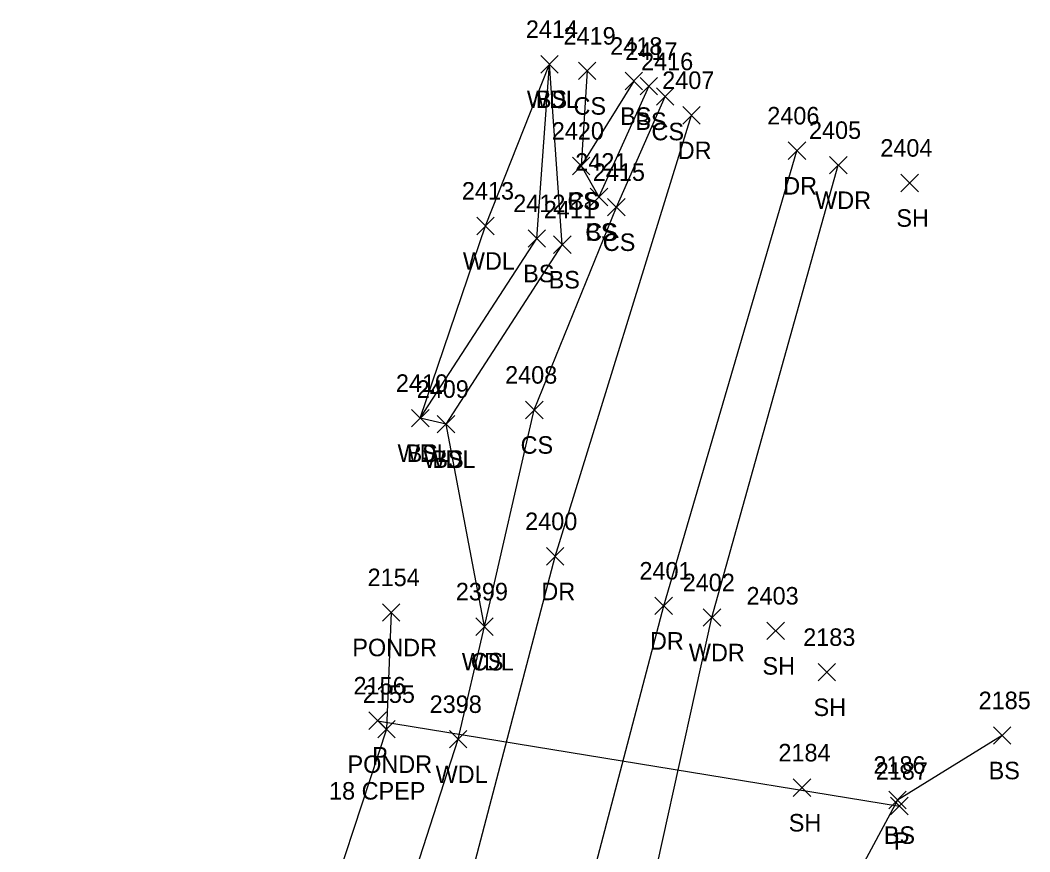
# Model space of a CAD drawing. Extents: x 1761340 to 1763889, y 696770 to 706023.
# Drawn here: x 1761653.6 to 1761768.9, y 701049.7 to 701144.6 of the extents above; entities that cross this region are included whole.
import ezdxf

# ---------------------------------------------------------------- set-up
doc = ezdxf.new("R2010")
doc.units = 0
for name, color, linetype in [('D_A', 7, 'Continuous'), ('D_C', 7, 'Continuous'), ('D_I', 7, 'Continuous'), ('D_TIC', 7, 'Continuous'), ('DCP', 7, 'Continuous'), ('L_A', 7, 'Continuous'), ('L_I', 7, 'Continuous'), ('L_TIC', 7, 'Continuous'), ('LAWA', 7, 'Continuous'), ('LAWE', 7, 'Continuous'), ('LELB', 7, 'Continuous'), ('R_A', 7, 'Continuous'), ('R_I', 7, 'Continuous'), ('R_TIC', 7, 'Continuous'), ('RDP', 7, 'Continuous')]:
    doc.layers.add(name, color=color, linetype=linetype)

msp = doc.modelspace()

# ---------------------------------------------------------------- linework, layer by layer
at = {"layer": 'D_TIC'}
for points in [[(1761693.43, 701063.63), (1761695.43, 701065.63)], [(1761695.43, 701063.63), (1761693.43, 701065.63)], [(1761752.98, 701053.9), (1761754.98, 701055.9)], [(1761754.98, 701053.9), (1761752.98, 701055.9)]]:
    msp.add_lwpolyline(points, dxfattribs=at)
at = {"layer": 'DCP'}
msp.add_lwpolyline([(1761694.43, 701064.63), (1761753.98, 701054.9)], dxfattribs=at)
at = {"layer": 'L_TIC'}
for points in [[(1761713.05, 701138.55), (1761715.05, 701140.55)], [(1761715.05, 701138.55), (1761713.05, 701140.55)], [(1761713.05, 701138.55), (1761715.05, 701140.55)], [(1761715.05, 701138.55), (1761713.05, 701140.55)], [(1761713.05, 701138.55), (1761715.05, 701140.55)], [(1761715.05, 701138.55), (1761713.05, 701140.55)], [(1761717.35, 701137.79), (1761719.35, 701139.79)], [(1761719.35, 701137.79), (1761717.35, 701139.79)], [(1761722.67, 701136.63), (1761724.67, 701138.63)], [(1761724.67, 701136.63), (1761722.67, 701138.63)], [(1761724.39, 701136.05), (1761726.39, 701138.05)], [(1761726.39, 701136.05), (1761724.39, 701138.05)], [(1761726.25, 701134.87), (1761728.25, 701136.87)], [(1761728.25, 701134.87), (1761726.25, 701136.87)], [(1761716.66, 701126.94), (1761718.66, 701128.94)], [(1761718.66, 701126.94), (1761716.66, 701128.94)], [(1761716.66, 701126.94), (1761718.66, 701128.94)], [(1761718.66, 701126.94), (1761716.66, 701128.94)], [(1761746, 701127.03), (1761748, 701129.03)], [(1761748, 701127.03), (1761746, 701129.03)], [(1761754.14, 701125), (1761756.14, 701127)], [(1761756.14, 701125), (1761754.14, 701127)], [(1761718.69, 701123.4), (1761720.69, 701125.4)], [(1761720.69, 701123.4), (1761718.69, 701125.4)], [(1761718.69, 701123.4), (1761720.69, 701125.4)], [(1761720.69, 701123.4), (1761718.69, 701125.4)], [(1761720.68, 701122.24), (1761722.68, 701124.24)], [(1761722.68, 701122.24), (1761720.68, 701124.24)], [(1761705.74, 701120.1), (1761707.74, 701122.1)], [(1761707.74, 701120.1), (1761705.74, 701122.1)], [(1761711.6, 701118.67), (1761713.6, 701120.67)], [(1761713.6, 701118.67), (1761711.6, 701120.67)], [(1761714.51, 701117.96), (1761716.51, 701119.96)], [(1761716.51, 701117.96), (1761714.51, 701119.96)], [(1761711.31, 701099.1), (1761713.31, 701101.1)], [(1761713.31, 701099.1), (1761711.31, 701101.1)], [(1761698.3, 701098.16), (1761700.3, 701100.16)], [(1761700.3, 701098.16), (1761698.3, 701100.16)], [(1761698.3, 701098.16), (1761700.3, 701100.16)], [(1761700.3, 701098.16), (1761698.3, 701100.16)], [(1761701.24, 701097.48), (1761703.24, 701099.48)], [(1761703.24, 701097.48), (1761701.24, 701099.48)], [(1761701.24, 701097.48), (1761703.24, 701099.48)], [(1761703.24, 701097.48), (1761701.24, 701099.48)], [(1761694.98, 701075.99), (1761696.98, 701077.99)], [(1761696.98, 701075.99), (1761694.98, 701077.99)], [(1761705.63, 701074.37), (1761707.63, 701076.37)], [(1761707.63, 701074.37), (1761705.63, 701076.37)], [(1761705.63, 701074.37), (1761707.63, 701076.37)], [(1761707.63, 701074.37), (1761705.63, 701076.37)], [(1761731.59, 701075.41), (1761733.59, 701077.41)], [(1761733.59, 701075.41), (1761731.59, 701077.41)], [(1761738.86, 701073.89), (1761740.86, 701075.89)], [(1761740.86, 701073.89), (1761738.86, 701075.89)], [(1761744.7, 701069.17), (1761746.7, 701071.17)], [(1761746.7, 701069.17), (1761744.7, 701071.17)], [(1761694.44, 701062.67), (1761696.44, 701064.67)], [(1761696.44, 701062.67), (1761694.44, 701064.67)], [(1761764.71, 701061.95), (1761766.71, 701063.95)], [(1761766.71, 701061.95), (1761764.71, 701063.95)], [(1761702.63, 701061.52), (1761704.63, 701063.52)], [(1761704.63, 701061.52), (1761702.63, 701063.52)], [(1761741.86, 701055.99), (1761743.86, 701057.99)], [(1761743.86, 701055.99), (1761741.86, 701057.99)], [(1761752.76, 701054.58), (1761754.76, 701056.58)], [(1761754.76, 701054.58), (1761752.76, 701056.58)]]:
    msp.add_lwpolyline(points, dxfattribs=at)
at = {"layer": 'LAWA'}
for points in [[(1761667.45, 700938.83), (1761676.85, 700965.95), (1761685.84, 701005.78), (1761682.94, 701010.81), (1761682.17, 701016.5), (1761683.01, 701019.11), (1761683.74, 701022.58), (1761694.2, 701030.75), (1761696.86, 701041.57), (1761703.63, 701062.52), (1761706.63, 701075.37), (1761702.24, 701098.48), (1761699.3, 701099.16), (1761706.74, 701121.1), (1761714.05, 701139.55)], [(1761683.19, 700893.77), (1761693.76, 700930.8), (1761702.56, 700960.09), (1761708.21, 700986.11), (1761709.81, 700994.41), (1761714.45, 701002.91), (1761720.39, 701013.78), (1761724.65, 701022.11), (1761723.36, 701026.16), (1761723.24, 701034.18), (1761732.59, 701076.41), (1761747, 701128.03)]]:
    msp.add_lwpolyline(points, dxfattribs=at)
at = {"layer": 'LAWE'}
msp.add_lwpolyline([(1761695.98, 701076.99), (1761695.44, 701063.67), (1761686.95, 701037.86), (1761683.04, 701033.21), (1761676.9, 701029.91)], dxfattribs=at)
at = {"layer": 'LELB'}
for points in [[(1761699.3, 701099.16), (1761712.6, 701119.67), (1761714.05, 701139.55)], [(1761702.24, 701098.48), (1761715.51, 701118.96), (1761714.05, 701139.55)], [(1761718.35, 701138.79), (1761717.66, 701127.94), (1761719.69, 701124.4)], [(1761723.67, 701137.63), (1761717.66, 701127.94)], [(1761725.39, 701137.05), (1761719.69, 701124.4)], [(1761706.63, 701075.37), (1761712.31, 701100.1), (1761721.68, 701123.24), (1761727.25, 701135.87)], [(1761765.71, 701062.95), (1761753.76, 701055.58), (1761746.39, 701041.84), (1761732.94, 701026.33), (1761734.36, 701016.2), (1761728.87, 701002.88)]]:
    msp.add_lwpolyline(points, dxfattribs=at)
at = {"layer": 'R_TIC'}
for points in [[(1761729.25, 701132.73), (1761731.25, 701134.73)], [(1761731.25, 701132.73), (1761729.25, 701134.73)], [(1761741.29, 701128.68), (1761743.29, 701130.68)], [(1761743.29, 701128.68), (1761741.29, 701130.68)], [(1761713.69, 701082.39), (1761715.69, 701084.39)], [(1761715.69, 701082.39), (1761713.69, 701084.39)], [(1761726.08, 701076.74), (1761728.08, 701078.74)], [(1761728.08, 701076.74), (1761726.08, 701078.74)]]:
    msp.add_lwpolyline(points, dxfattribs=at)
at = {"layer": 'RDP'}
for points in [[(1761671.26, 700538.43), (1761661.64, 700574.62), (1761657.61, 700611.79), (1761653.18, 700645.74), (1761649.93, 700682.03), (1761646.9, 700721.23), (1761649.1, 700763.06), (1761651.35, 700791.61), (1761653.66, 700826.22), (1761659.48, 700861.88), (1761668.31, 700899.37), (1761676.77, 700936.6), (1761684.87, 700963.93), (1761695.51, 701007.43), (1761695.75, 701009.14), (1761702.96, 701038.72), (1761714.69, 701083.39), (1761730.25, 701133.73)], [(1761685.9, 700541.84), (1761678.4, 700578.09), (1761669.59, 700613.17), (1761665.81, 700647.63), (1761660.31, 700684.32), (1761659.55, 700721.03), (1761658.73, 700762.09), (1761660.8, 700791.69), (1761663.62, 700822.45), (1761666.15, 700836.34), (1761667.52, 700847.08), (1761668.95, 700859.68), (1761676.88, 700896.8), (1761686.16, 700933.2), (1761693.93, 700961.97), (1761704.59, 700998.32), (1761705.06, 700999.04), (1761715.84, 701034.88), (1761727.08, 701077.74), (1761742.29, 701129.68)]]:
    msp.add_lwpolyline(points, dxfattribs=at)

# ---------------------------------------------------------------- texts
at = {"layer": 'D_A'}
for p in [(1761693.8, 701059.63), (1761753.35, 701049.9)]:
    msp.add_text('P', height=2, dxfattribs=at).set_placement(p)
at = {"layer": 'D_C'}
msp.add_text('18 CPEP', height=2, dxfattribs=at).set_placement((1761688.89, 701055.63))
at = {"layer": 'D_I'}
for s, p in [('2156', (1761691.68, 701067.63)), ('2187', (1761751.28, 701057.9))]:
    msp.add_text(s, height=2, dxfattribs=at).set_placement(p)
at = {"layer": 'L_A'}
for s, p in [('WDL', (1761711.46, 701134.55)), ('BS', (1761712.49, 701134.55)), ('BS', (1761712.49, 701134.55)), ('CS', (1761716.79, 701133.79)), ('BS', (1761722.11, 701132.63)), ('BS', (1761723.84, 701132.05)), ('CS', (1761725.69, 701130.87)), ('CS', (1761716.1, 701122.94)), ('BS', (1761716.1, 701122.94)), ('WDR', (1761744.36, 701123.03)), ('SH', (1761753.63, 701121)), ('CS', (1761718.13, 701119.4)), ('BS', (1761718.13, 701119.4)), ('CS', (1761720.13, 701118.24)), ('WDL', (1761704.16, 701116.1)), ('BS', (1761711.04, 701114.67)), ('BS', (1761713.95, 701113.96)), ('CS', (1761710.75, 701095.1)), ('WDL', (1761696.71, 701094.16)), ('BS', (1761697.74, 701094.16)), ('WDL', (1761699.66, 701093.48)), ('BS', (1761700.68, 701093.48)), ('PONDR', (1761691.55, 701071.99)), ('WDR', (1761729.95, 701071.41)), ('WDL', (1761704.04, 701070.37)), ('CS', (1761705.07, 701070.37)), ('SH', (1761738.35, 701069.89)), ('SH', (1761744.18, 701065.17)), ('PONDR', (1761691, 701058.67)), ('WDL', (1761701.05, 701057.52)), ('BS', (1761764.16, 701057.95)), ('SH', (1761741.35, 701051.99)), ('BS', (1761752.2, 701050.58))]:
    msp.add_text(s, height=2, dxfattribs=at).set_placement(p)
at = {"layer": 'L_I'}
for s, p in [('2414', (1761711.35, 701142.55)), ('2414', (1761711.35, 701142.55)), ('2414', (1761711.35, 701142.55)), ('2419', (1761715.65, 701141.79)), ('2418', (1761720.98, 701140.63)), ('2417', (1761722.7, 701140.05)), ('2416', (1761724.5, 701138.87)), ('2420', (1761714.31, 701130.94)), ('2420', (1761714.31, 701130.94)), ('2405', (1761743.66, 701131.03)), ('2404', (1761751.8, 701129)), ('2421', (1761716.99, 701127.4)), ('2421', (1761716.99, 701127.4)), ('2415', (1761718.99, 701126.24)), ('2413', (1761704.05, 701124.1)), ('2412', (1761709.91, 701122.67)), ('2411', (1761713.39, 701121.96)), ('2410', (1761696.52, 701102.16)), ('2410', (1761696.52, 701102.16)), ('2408', (1761708.98, 701103.1)), ('2409', (1761698.89, 701101.48)), ('2409', (1761698.89, 701101.48)), ('2154', (1761693.29, 701079.99)), ('2402', (1761729.25, 701079.41)), ('2399', (1761703.36, 701078.37)), ('2399', (1761703.36, 701078.37)), ('2403', (1761736.53, 701077.89)), ('2183', (1761743, 701073.17)), ('2155', (1761692.74, 701066.67)), ('2398', (1761700.37, 701065.52)), ('2185', (1761763.02, 701065.95)), ('2184', (1761740.17, 701059.99)), ('2186', (1761751.01, 701058.58))]:
    msp.add_text(s, height=2, dxfattribs=at).set_placement(p)
at = {"layer": 'R_A'}
for p in [(1761728.68, 701128.73), (1761740.72, 701124.68), (1761713.12, 701078.39), (1761725.51, 701072.74)]:
    msp.add_text('DR', height=2, dxfattribs=at).set_placement(p)
at = {"layer": 'R_I'}
for s, p in [('2407', (1761726.91, 701136.73)), ('2406', (1761738.9, 701132.68)), ('2400', (1761711.27, 701086.39)), ('2401', (1761724.31, 701080.74))]:
    msp.add_text(s, height=2, dxfattribs=at).set_placement(p)

doc.saveas('drawing.dxf')
